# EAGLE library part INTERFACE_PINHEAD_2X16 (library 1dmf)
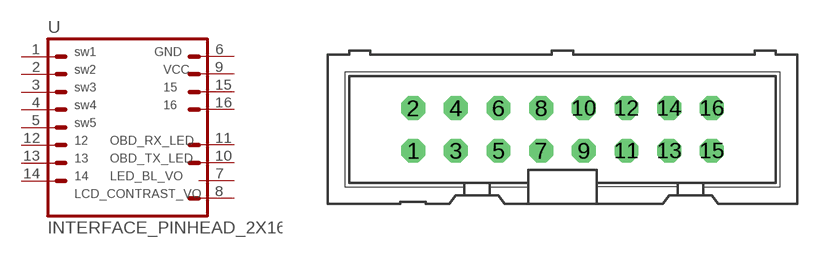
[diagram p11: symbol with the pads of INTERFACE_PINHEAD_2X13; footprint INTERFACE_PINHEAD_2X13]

Designator prefix -

## INTERFACE_PINHEAD_2X16  [INTERFACE_PINHEAD_2X13]
1  SW1  pas
2  SW2  pas
3  SW3  pas
4  SW4  pas
5  SW5  pas
6  GND  pas
7  LED_BL_VO  pas
8  LCD_CONTRAST_VO  pas
9  VCC  pas
10  OBD_TX_LED  pas
11  OBD_RX_LED  pas
12  12  pas
13  13  pas
14  14  pas
15  15  pas
16  16  pas

## Footprint INTERFACE_PINHEAD_2X13 (pad centres in mm)
drill 0.914 octagon: 1 -8.89,-1.27; 2 -8.89,1.27; 3 -6.35,-1.27; 4 -6.35,1.27; 5 -3.81,-1.27; 6 -3.81,1.27; 7 -1.27,-1.27; 8 -1.27,1.27; 9 1.27,-1.27; 10 1.27,1.27; 11 3.81,-1.27; 12 3.81,1.27; 13 6.35,-1.27; 14 6.35,1.27; 15 8.89,-1.27; 16 8.89,1.27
